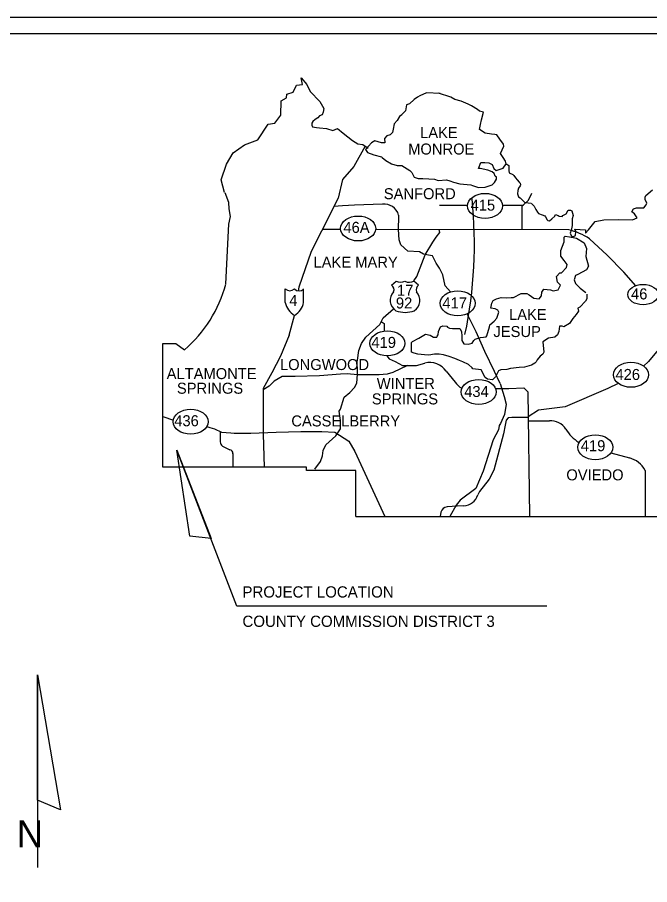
# Model space of a CAD drawing. Extents: x 2157516 to 2331756, y 2153820 to 2265756.
# Drawn here: x 2268726 to 2310288, y 2208739 to 2265756 of the extents above; entities that cross this region are included whole.
import ezdxf

# ---------------------------------------------------------------- set-up
doc = ezdxf.new("R2010")
doc.units = 0
for name, color, linetype in [('Default', 7, 'Continuous'), ('NorthArw_dp', 7, 'Continuous'), ('PlotBorder_dp', 7, 'Continuous'), ('SheetBorder_dp', 7, 'Continuous'), ('TextLabel', 7, 'Continuous')]:
    doc.layers.add(name, color=color, linetype=linetype)

msp = doc.modelspace()

# ---------------------------------------------------------------- linework, layer by layer
at = {"layer": 'Default'}
for p, q in [((2286861, 2260837), (2287074, 2261301)), ((2287074, 2261301), (2287461, 2261340)), ((2287461, 2261339), (2287384, 2261784)), ((2287384, 2261784), (2287751, 2261339)), ((2287751, 2261340), (2287984, 2260876)), ((2286436, 2260702), (2286861, 2260837)), ((2287984, 2260876), (2288603, 2260218)), ((2295622, 2260801), (2295179, 2260600)), ((2296508, 2260741), (2295622, 2260801)), ((2297212, 2260499), (2296407, 2260761)), ((2286049, 2259329), (2286068, 2260276)), ((2286068, 2260276), (2286417, 2260470)), ((2286417, 2260470), (2286436, 2260702)), ((2288603, 2260218), (2288873, 2259754)), ((2294817, 2260358), (2294494, 2260076)), ((2295038, 2260499), (2294817, 2260358)), ((2295179, 2260600), (2295038, 2260499)), ((2297474, 2260358), (2297212, 2260499)), ((2297897, 2260237), (2297474, 2260358)), ((2298360, 2260056), (2297897, 2260237)), ((2288873, 2259754), (2288835, 2259522)), ((2294233, 2259613), (2294031, 2259391)), ((2294313, 2259996), (2294233, 2259613)), ((2294494, 2260076), (2294313, 2259996)), ((2298581, 2259935), (2298360, 2260056)), ((2298964, 2259694), (2298581, 2259935)), ((2299105, 2259593), (2298964, 2259694)), ((2299366, 2259512), (2299105, 2259593)), ((2285643, 2258806), (2286049, 2259329)), ((2288293, 2259039), (2288138, 2258903)), ((2288486, 2259155), (2288293, 2259039)), ((2288583, 2259271), (2288486, 2259155)), ((2288757, 2259348), (2288583, 2259271)), ((2288835, 2259522), (2288757, 2259348)), ((2293850, 2259230), (2293689, 2258969)), ((2293991, 2259351), (2293850, 2259230)), ((2294031, 2259391), (2293991, 2259351)), ((2299165, 2258707), (2299225, 2259029)), ((2299225, 2259029), (2299366, 2259512)), ((2284539, 2257693), (2285216, 2258737)), ((2285216, 2258737), (2285643, 2258806)), ((2288138, 2258903), (2288080, 2258806)), ((2288080, 2258806), (2288080, 2258671)), ((2288080, 2258671), (2288119, 2258555)), ((2288119, 2258555), (2288390, 2258516)), ((2288390, 2258516), (2288583, 2258497)), ((2288583, 2258497), (2289048, 2258439)), ((2289048, 2258439), (2289454, 2258323)), ((2289454, 2258323), (2289763, 2258458)), ((2289763, 2258458), (2290150, 2258149)), ((2293488, 2258747), (2293427, 2258405)), ((2293689, 2258969), (2293488, 2258747)), ((2299105, 2258384), (2299165, 2258707)), ((2290150, 2258149), (2290750, 2257665)), ((2293005, 2257962), (2292864, 2257800)), ((2293226, 2258042), (2293005, 2257962)), ((2293387, 2258183), (2293226, 2258042)), ((2293427, 2258405), (2293387, 2258183)), ((2299487, 2258143), (2299105, 2258384)), ((2299890, 2258082), (2299487, 2258143)), ((2300111, 2258062), (2299890, 2258082)), ((2300252, 2258022), (2300111, 2258062)), ((2300433, 2257740), (2300252, 2258022)), ((2282914, 2256842), (2283649, 2257384)), ((2283649, 2257384), (2284539, 2257693)), ((2290750, 2257665), (2291098, 2257431)), ((2291098, 2257431), (2291426, 2257392)), ((2291426, 2257392), (2291794, 2257160)), ((2291998, 2257498), (2291616, 2257075)), ((2292220, 2257639), (2291998, 2257498)), ((2292662, 2257498), (2292220, 2257639)), ((2292884, 2257498), (2292662, 2257498)), ((2292864, 2257800), (2292884, 2257498)), ((2300675, 2257418), (2300433, 2257740)), ((2300695, 2257277), (2300675, 2257418)), ((2282469, 2256107), (2282914, 2256842)), ((2291587, 2257291), (2290854, 2255947)), ((2291616, 2257075), (2291736, 2256874)), ((2291736, 2256874), (2292159, 2256713)), ((2300494, 2256814), (2300695, 2257277)), ((2300655, 2256552), (2300494, 2256814)), ((2292159, 2256713), (2292662, 2256592)), ((2292662, 2256592), (2292703, 2256532)), ((2292703, 2256532), (2292944, 2256350)), ((2292944, 2256350), (2293327, 2256129)), ((2299044, 2255827), (2299185, 2256210)), ((2299185, 2256210), (2299447, 2256210)), ((2299447, 2256210), (2299708, 2256189)), ((2299708, 2256189), (2299930, 2256089)), ((2300816, 2256310), (2300655, 2256552)), ((2300856, 2256129), (2300816, 2256310)), ((2282121, 2255063), (2282469, 2256107)), ((2290854, 2255947), (2290107, 2255085)), ((2293327, 2256129), (2293689, 2256008)), ((2293689, 2256008), (2293951, 2256008)), ((2293951, 2256008), (2293991, 2256008)), ((2293991, 2256008), (2294172, 2255907)), ((2294172, 2255907), (2294515, 2255686)), ((2294515, 2255686), (2294655, 2255545)), ((2299145, 2255827), (2299044, 2255827)), ((2299648, 2255706), (2299145, 2255827)), ((2299930, 2255605), (2299648, 2255706)), ((2299930, 2256089), (2300051, 2255827)), ((2300071, 2255485), (2299930, 2255605)), ((2300051, 2255827), (2300192, 2255686)), ((2300192, 2255686), (2300655, 2255847)), ((2300655, 2255847), (2300856, 2256129)), ((2300856, 2256129), (2300897, 2256102)), ((2300897, 2256102), (2301032, 2256025)), ((2301032, 2256025), (2301032, 2255696)), ((2301032, 2255696), (2301052, 2255542)), ((2282353, 2254231), (2282121, 2255063)), ((2290107, 2255085), (2289820, 2253878)), ((2294655, 2255545), (2294817, 2255243)), ((2294817, 2255243), (2295078, 2255162)), ((2295078, 2255162), (2295380, 2255162)), ((2295380, 2255162), (2295783, 2255142)), ((2295783, 2255142), (2296145, 2255122)), ((2296145, 2255122), (2296387, 2255021)), ((2296387, 2255021), (2296930, 2255082)), ((2296930, 2255082), (2297152, 2255001)), ((2300131, 2255323), (2300071, 2255485)), ((2300091, 2254901), (2300212, 2255122)), ((2300212, 2255243), (2300131, 2255323)), ((2300212, 2255122), (2300212, 2255243)), ((2301052, 2255542), (2301303, 2255425)), ((2301303, 2255425), (2301361, 2255367)), ((2301361, 2255367), (2301477, 2255213)), ((2301477, 2255213), (2301574, 2255077)), ((2301574, 2255077), (2301709, 2254923)), ((2297152, 2255001), (2297393, 2254921)), ((2297393, 2254921), (2297816, 2254820)), ((2297816, 2254820), (2298541, 2254739)), ((2298541, 2254739), (2298642, 2254699)), ((2298642, 2254699), (2299044, 2254578)), ((2299044, 2254578), (2299487, 2254598)), ((2299487, 2254598), (2299930, 2254739)), ((2299930, 2254739), (2300091, 2254901)), ((2301671, 2254536), (2301613, 2254362)), ((2301787, 2254671), (2301671, 2254536)), ((2301709, 2254923), (2301787, 2254845)), ((2301787, 2254845), (2301806, 2254749)), ((2301806, 2254749), (2301787, 2254671)), ((2282624, 2253574), (2282391, 2254212)), ((2289820, 2253878), (2288728, 2251694)), ((2301613, 2254362), (2301593, 2254149)), ((2301593, 2254149), (2301613, 2254091)), ((2301613, 2254091), (2301671, 2253956)), ((2301671, 2253956), (2301768, 2253898)), ((2301768, 2253898), (2301864, 2253801)), ((2302328, 2253731), (2302536, 2254206)), ((2309996, 2253944), (2310030, 2254044)), ((2309996, 2253776), (2309996, 2253944)), ((2310030, 2254044), (2310465, 2254412)), ((2282643, 2253168), (2282624, 2253574)), ((2290107, 2253374), (2289534, 2253330)), ((2290879, 2253418), (2290107, 2253374)), ((2292732, 2253485), (2290879, 2253418)), ((2296479, 2253412), (2298323, 2253412)), ((2300622, 2253412), (2301994, 2253412)), ((2301864, 2253801), (2302058, 2253608)), ((2301913, 2253346), (2302328, 2253731)), ((2301913, 2251804), (2301913, 2253346)), ((2302058, 2253608), (2302309, 2253569)), ((2302309, 2253569), (2302503, 2253530)), ((2302522, 2253511), (2302691, 2253338)), ((2302691, 2253338), (2302807, 2253125)), ((2309896, 2253241), (2310063, 2253441)), ((2310097, 2253542), (2309996, 2253776)), ((2310063, 2253441), (2310097, 2253542)), ((2282740, 2252665), (2282643, 2253168)), ((2293784, 2251729), (2293791, 2252757)), ((2302807, 2253125), (2302923, 2252951)), ((2302923, 2252951), (2302981, 2252854)), ((2302981, 2252854), (2303213, 2252777)), ((2303213, 2252777), (2303406, 2252699)), ((2304064, 2252680), (2304103, 2252796)), ((2304103, 2252796), (2304277, 2252738)), ((2304277, 2252738), (2304335, 2252680)), ((2304586, 2252719), (2304799, 2252835)), ((2304799, 2252835), (2304935, 2253086)), ((2304935, 2253086), (2305089, 2253086)), ((2305089, 2253086), (2305167, 2253028)), ((2305167, 2253028), (2305264, 2252738)), ((2305264, 2252738), (2305206, 2252506)), ((2309126, 2252973), (2309226, 2253174)), ((2309293, 2252839), (2309126, 2252973)), ((2309226, 2253174), (2309427, 2253241)), ((2309461, 2252571), (2309293, 2252839)), ((2309427, 2253241), (2309661, 2253241)), ((2309661, 2253241), (2309896, 2253241)), ((2282421, 2248226), (2282628, 2252165)), ((2282628, 2252165), (2282740, 2252665)), ((2303406, 2252699), (2303445, 2252641)), ((2303445, 2252641), (2303542, 2252448)), ((2303542, 2252448), (2303600, 2252390)), ((2303600, 2252390), (2303716, 2252371)), ((2303716, 2252371), (2303851, 2252506)), ((2303851, 2252506), (2304064, 2252680)), ((2304335, 2252680), (2304528, 2252661)), ((2304528, 2252661), (2304586, 2252719)), ((2305206, 2252506), (2305186, 2252216)), ((2305186, 2252216), (2305206, 2252081)), ((2306270, 2251790), (2306716, 2252337)), ((2306716, 2252337), (2307285, 2252437)), ((2307285, 2252437), (2308222, 2252471)), ((2308222, 2252471), (2309159, 2252437)), ((2309159, 2252437), (2309461, 2252571)), ((2288728, 2251694), (2288039, 2250372)), ((2289980, 2251802), (2288782, 2251802)), ((2304966, 2251796), (2292275, 2251801)), ((2293823, 2251130), (2293779, 2251800)), ((2296263, 2251300), (2296492, 2251622)), ((2296492, 2251622), (2296446, 2251805)), ((2305128, 2251752), (2305070, 2251558)), ((2305206, 2252081), (2305128, 2251752)), ((2305438, 2251674), (2305360, 2251829)), ((2305360, 2251829), (2306076, 2251790)), ((2305418, 2251423), (2305438, 2251674)), ((2306076, 2251790), (2306076, 2251578)), ((2306076, 2251578), (2306270, 2251790)), ((2293935, 2250794), (2293823, 2251130)), ((2296033, 2250979), (2296263, 2251300)), ((2304671, 2251305), (2304733, 2251368)), ((2304671, 2250994), (2304671, 2251305)), ((2304733, 2251368), (2305013, 2251336)), ((2305013, 2251336), (2305480, 2251243)), ((2305070, 2251558), (2305128, 2251404)), ((2305128, 2251404), (2305244, 2251326)), ((2305244, 2251326), (2305418, 2251423)), ((2305480, 2251243), (2305979, 2250932)), ((2307505, 2250127), (2306339, 2251204)), ((2294383, 2250384), (2293935, 2250794)), ((2295530, 2250144), (2296033, 2250979)), ((2304453, 2250433), (2304671, 2250994)), ((2305979, 2250932), (2306134, 2250558)), ((2306134, 2250558), (2306103, 2250028)), ((2288039, 2250372), (2287234, 2248016)), ((2295166, 2250347), (2294383, 2250384)), ((2294979, 2248721), (2295530, 2250144)), ((2295426, 2250198), (2295166, 2250347)), ((2295762, 2250123), (2295426, 2250198)), ((2296023, 2250086), (2295762, 2250123)), ((2296247, 2249601), (2296023, 2250086)), ((2304453, 2250059), (2304453, 2250433)), ((2304671, 2249779), (2304453, 2250059)), ((2306103, 2250028), (2306259, 2249405)), ((2308582, 2249005), (2307505, 2250127)), ((2296470, 2249265), (2296247, 2249601)), ((2304858, 2249498), (2304671, 2249779)), ((2304827, 2249312), (2304858, 2249498)), ((2306259, 2249405), (2306134, 2249156)), ((2296694, 2248818), (2296470, 2249265)), ((2296843, 2248109), (2296694, 2248818)), ((2304173, 2248720), (2304391, 2248969)), ((2304391, 2248969), (2304484, 2248969)), ((2304484, 2248969), (2304827, 2249312)), ((2305418, 2248782), (2305325, 2248502)), ((2305574, 2248844), (2305418, 2248782)), ((2306134, 2249156), (2305574, 2248844)), ((2309370, 2248116), (2308582, 2249005)), ((2293323, 2248147), (2293628, 2248417)), ((2294784, 2248427), (2294979, 2248721)), ((2295101, 2248147), (2294796, 2248417)), ((2304235, 2248346), (2304173, 2248720)), ((2304422, 2248159), (2304235, 2248346)), ((2305325, 2248502), (2305418, 2248252)), ((2305418, 2248252), (2305730, 2247941)), ((2286337, 2247013), (2286337, 2247912)), ((2287234, 2248016), (2287187, 2247780)), ((2287543, 2247013), (2287543, 2247912)), ((2297199, 2247705), (2296843, 2248109)), ((2303176, 2247442), (2303207, 2247692)), ((2303207, 2247692), (2303332, 2247878)), ((2303332, 2247878), (2303768, 2247847)), ((2303768, 2247847), (2303955, 2247785)), ((2303955, 2247785), (2304266, 2247847)), ((2304266, 2247847), (2304422, 2248159)), ((2305730, 2247941), (2306103, 2247660)), ((2299907, 2246975), (2300000, 2247131)), ((2300000, 2247131), (2300218, 2247255)), ((2300218, 2247255), (2300530, 2247349)), ((2300530, 2247349), (2300903, 2247318)), ((2300903, 2247318), (2301183, 2247349)), ((2301183, 2247349), (2301339, 2247349)), ((2301339, 2247349), (2301837, 2247598)), ((2301837, 2247598), (2302211, 2247598)), ((2302211, 2247598), (2302367, 2247505)), ((2302367, 2247505), (2302678, 2247287)), ((2302678, 2247287), (2303021, 2247255)), ((2303021, 2247255), (2303176, 2247442)), ((2306072, 2247100), (2305698, 2246695)), ((2306166, 2247255), (2306072, 2247100)), ((2306166, 2247567), (2306166, 2247255)), ((2292776, 2246012), (2293453, 2246599)), ((2299844, 2246632), (2299907, 2246975)), ((2300125, 2246601), (2299844, 2246632)), ((2300312, 2246508), (2300125, 2246601)), ((2300374, 2246383), (2300312, 2246508)), ((2305698, 2246695), (2305574, 2246632)), ((2305574, 2246632), (2305605, 2246445)), ((2286602, 2244855), (2286940, 2246160)), ((2292547, 2245553), (2292776, 2246012)), ((2298894, 2245088), (2298288, 2246263)), ((2300062, 2245791), (2300249, 2245978)), ((2300249, 2245978), (2300374, 2246383)), ((2305231, 2245947), (2305013, 2245635)), ((2305449, 2246227), (2305231, 2245947)), ((2305605, 2246445), (2305449, 2246227)), ((2291629, 2244726), (2292547, 2245553)), ((2292647, 2245754), (2292846, 2245635)), ((2292846, 2245635), (2292846, 2245134)), ((2296419, 2245106), (2296544, 2245417)), ((2296544, 2245417), (2296700, 2245480)), ((2296700, 2245480), (2296949, 2245448)), ((2296949, 2245448), (2297011, 2245386)), ((2297011, 2245386), (2297135, 2245324)), ((2297135, 2245324), (2297322, 2245293)), ((2299595, 2244825), (2299751, 2245417)), ((2299751, 2245417), (2299782, 2245542)), ((2299782, 2245542), (2300062, 2245791)), ((2304360, 2245448), (2304328, 2245106)), ((2304546, 2245448), (2304360, 2245448)), ((2304640, 2245417), (2304546, 2245448)), ((2305013, 2245635), (2304640, 2245417)), ((2286602, 2244855), (2286028, 2243476)), ((2295124, 2244659), (2295558, 2244930)), ((2295558, 2244930), (2295859, 2244857)), ((2295859, 2244857), (2296077, 2244732)), ((2296295, 2244732), (2296326, 2244794)), ((2296326, 2244794), (2296388, 2244888)), ((2296388, 2244888), (2296419, 2245106)), ((2297322, 2245293), (2297571, 2245293)), ((2297571, 2245293), (2297821, 2245293)), ((2297821, 2245293), (2297914, 2245106)), ((2297914, 2245106), (2297945, 2244794)), ((2297945, 2244794), (2297945, 2244670)), ((2299453, 2243783), (2298894, 2245088)), ((2299377, 2244732), (2299533, 2244763)), ((2299533, 2244763), (2299595, 2244825)), ((2304235, 2244888), (2304048, 2244732)), ((2304328, 2245106), (2304235, 2244888)), ((2278294, 2236185), (2278294, 2244325)), ((2278294, 2244325), (2279159, 2244325)), ((2278294, 2244325), (2279140, 2244325)), ((2279140, 2244325), (2279703, 2243894)), ((2291170, 2243854), (2291353, 2244313)), ((2291353, 2244313), (2291629, 2244726)), ((2294636, 2244387), (2294690, 2244441)), ((2294636, 2244224), (2294636, 2244387)), ((2294636, 2244007), (2294636, 2244224)), ((2294690, 2244441), (2295124, 2244659)), ((2296077, 2244732), (2296170, 2244732)), ((2296170, 2244732), (2296295, 2244732)), ((2297945, 2244670), (2297945, 2244514)), ((2297945, 2244514), (2298070, 2244296)), ((2298070, 2244296), (2298350, 2244265)), ((2298350, 2244265), (2298630, 2244327)), ((2298630, 2244327), (2298724, 2244514)), ((2298724, 2244514), (2298817, 2244607)), ((2298817, 2244607), (2299159, 2244701)), ((2299159, 2244701), (2299377, 2244732)), ((2303643, 2244670), (2303270, 2244420)), ((2303270, 2244420), (2303332, 2243735)), ((2304048, 2244732), (2303643, 2244670)), ((2291078, 2243211), (2291170, 2243854)), ((2294644, 2243735), (2294644, 2244078)), ((2294800, 2243673), (2294644, 2243735)), ((2295049, 2243610), (2294800, 2243673)), ((2300086, 2242478), (2299453, 2243783)), ((2303332, 2243735), (2303270, 2243610)), ((2310855, 2243899), (2310204, 2243139)), ((2286028, 2243476), (2285453, 2242384)), ((2291032, 2243028), (2291078, 2243211)), ((2293009, 2243504), (2293171, 2243302)), ((2293171, 2243302), (2293551, 2243139)), ((2293551, 2243139), (2294039, 2242867)), ((2295485, 2243579), (2295049, 2243610)), ((2295765, 2243548), (2295485, 2243579)), ((2296139, 2243610), (2295765, 2243548)), ((2296450, 2243610), (2296139, 2243610)), ((2296731, 2243579), (2296450, 2243610)), ((2297104, 2243455), (2296731, 2243579)), ((2297478, 2243330), (2297104, 2243455)), ((2297789, 2243205), (2297478, 2243330)), ((2298007, 2243112), (2297789, 2243205)), ((2298381, 2242925), (2298007, 2243112)), ((2302834, 2243112), (2302740, 2243019)), ((2302896, 2243237), (2302834, 2243112)), ((2303083, 2243486), (2302896, 2243237)), ((2303270, 2243610), (2303083, 2243486)), ((2310204, 2243139), (2309880, 2242833)), ((2291078, 2242706), (2291032, 2243028)), ((2291078, 2242293), (2291078, 2242706)), ((2294375, 2242867), (2293398, 2242402)), ((2294039, 2242867), (2294419, 2242867)), ((2294419, 2242867), (2294961, 2242867)), ((2294961, 2242867), (2295504, 2243030)), ((2296914, 2242488), (2297511, 2241782)), ((2298630, 2242707), (2298381, 2242925)), ((2298661, 2242645), (2298630, 2242707)), ((2299222, 2242582), (2298661, 2242645)), ((2299471, 2242084), (2299222, 2242582)), ((2300459, 2241694), (2300086, 2242478)), ((2300343, 2242520), (2300156, 2242115)), ((2300498, 2242582), (2300343, 2242520)), ((2300903, 2242614), (2300498, 2242582)), ((2301152, 2242676), (2300903, 2242614)), ((2301713, 2242738), (2301152, 2242676)), ((2302055, 2242769), (2301713, 2242738)), ((2302211, 2242800), (2302055, 2242769)), ((2302522, 2242894), (2302211, 2242800)), ((2302740, 2243019), (2302522, 2242894)), ((2285453, 2242384), (2284883, 2241351)), ((2286128, 2242141), (2285606, 2241843)), ((2286986, 2242141), (2286128, 2242141)), ((2288589, 2242178), (2286986, 2242141)), ((2289968, 2242290), (2288589, 2242178)), ((2290416, 2242328), (2289968, 2242290)), ((2291087, 2242253), (2290416, 2242328)), ((2291032, 2241696), (2291078, 2242293)), ((2291832, 2242253), (2291087, 2242253)), ((2292503, 2242253), (2291832, 2242253)), ((2293025, 2242290), (2292503, 2242253)), ((2293398, 2242402), (2293025, 2242290)), ((2299627, 2241959), (2299471, 2242084)), ((2299969, 2241928), (2299627, 2241959)), ((2300156, 2242115), (2299969, 2241928)), ((2285271, 2241507), (2284883, 2241268)), ((2284883, 2241351), (2284883, 2238362)), ((2285606, 2241843), (2285271, 2241507)), ((2290573, 2241099), (2290894, 2241421)), ((2290894, 2241421), (2291032, 2241696)), ((2300161, 2241348), (2301037, 2241348)), ((2300459, 2241694), (2300718, 2240841)), ((2301037, 2241348), (2302013, 2241402)), ((2302013, 2241402), (2302284, 2241131)), ((2307546, 2241348), (2304726, 2240154)), ((2308219, 2241695), (2307546, 2241348)), ((2289977, 2239997), (2290206, 2240778)), ((2290206, 2240778), (2290573, 2241099)), ((2300718, 2240841), (2300867, 2240318)), ((2302284, 2241131), (2302391, 2232944)), ((2300867, 2240318), (2300755, 2239647)), ((2289885, 2239860), (2289977, 2239997)), ((2289977, 2239263), (2289885, 2239860)), ((2300755, 2239647), (2300481, 2239046)), ((2302990, 2239937), (2302306, 2239494)), ((2304726, 2240154), (2302990, 2239937)), ((2278294, 2239522), (2278980, 2239282)), ((2289977, 2238712), (2289977, 2239263)), ((2300867, 2239274), (2300792, 2238939)), ((2300979, 2239423), (2300867, 2239274)), ((2301227, 2239456), (2300979, 2239423)), ((2302271, 2239456), (2301227, 2239456)), ((2302309, 2239231), (2303695, 2239231)), ((2281185, 2238857), (2281369, 2238791)), ((2281369, 2238791), (2281675, 2238706)), ((2281675, 2238706), (2282150, 2238486)), ((2282060, 2238527), (2282060, 2237840)), ((2282150, 2238486), (2282750, 2238448)), ((2285745, 2238477), (2287353, 2238535)), ((2287353, 2238535), (2288732, 2238535)), ((2288732, 2238535), (2289594, 2238477)), ((2289655, 2238253), (2289977, 2238712)), ((2300357, 2238634), (2300006, 2237983)), ((2300407, 2238934), (2300357, 2238634)), ((2300481, 2239046), (2300407, 2238934)), ((2300792, 2238939), (2300680, 2238379)), ((2282750, 2238448), (2282987, 2238420)), ((2282987, 2238420), (2284078, 2238420)), ((2284078, 2238420), (2285745, 2238477)), ((2284883, 2238362), (2284940, 2236178)), ((2289013, 2237656), (2289655, 2238253)), ((2289594, 2238477), (2290513, 2237903)), ((2300006, 2237983), (2299355, 2235920)), ((2300680, 2238379), (2300047, 2235992)), ((2282204, 2237573), (2282474, 2237423)), ((2282474, 2237423), (2282684, 2237333)), ((2288829, 2237289), (2289013, 2237656)), ((2290513, 2237903), (2290916, 2237213)), ((2283159, 2227056), (2279217, 2237311)), ((2282900, 2237072), (2282900, 2236196)), ((2288646, 2236554), (2288783, 2236921)), ((2288783, 2236921), (2288829, 2237289)), ((2290916, 2237213), (2292881, 2232944)), ((2307743, 2237126), (2308957, 2236789)), ((2288278, 2236049), (2288646, 2236554)), ((2287727, 2236185), (2278294, 2236185)), ((2287727, 2235969), (2287727, 2236185)), ((2290968, 2235969), (2287727, 2235969)), ((2290968, 2232944), (2290968, 2235969)), ((2299355, 2235920), (2298867, 2234781)), ((2300047, 2235992), (2299748, 2235396)), ((2309988, 2235975), (2309988, 2232935)), ((2299748, 2235396), (2299095, 2234584)), ((2298867, 2234781), (2297836, 2234021)), ((2299095, 2234584), (2298987, 2234368)), ((2297836, 2234021), (2297565, 2233695)), ((2297631, 2233627), (2296971, 2233578)), ((2297565, 2233695), (2297165, 2232944)), ((2298063, 2233643), (2297631, 2233627)), ((2290968, 2232944), (2323515, 2232944)), ((2296568, 2233226), (2296515, 2232944)), ((2303540, 2227056), (2283159, 2227056))]:
    msp.add_line(p, q, dxfattribs=at)
msp.add_lwpolyline([(2279217, 2237311), (2281456, 2231487), (2280073, 2231648)], close=True, dxfattribs=at)
for centre, radius, start, end in [((2292818, 2252476), 1012, 16.0958, 94.902), ((2269936, 2250856), 28834, 348.105, 5.8904), ((2303688, 2246949), 5013, 58.0781, 75.228), ((2274239, 2250342), 8452, 310.2757, 345.4975), ((2293922, 2249045), 694, 244.9344, 293.0494), ((2294484, 2249030), 688, 244.9903, 296.9038), ((2286645, 2248227), 440, 225.6466, 312.1907), ((2287248, 2248216), 440, 225.6466, 312.1907), ((2294053, 2247152), 816, 136.8231, 236.7608), ((2293122, 2247846), 363, 338.0393, 56.3707), ((2294370, 2247152), 816, 303.2392, 43.1769), ((2295301, 2247846), 363, 123.6293, 201.9607), ((2287615, 2247278), 1306, 191.7069, 238.8545), ((2286265, 2247278), 1306, 301.1455, 348.2931), ((2294212, 2248095), 1734, 249.5588, 290.4412), ((2295829, 2241772), 1300, 33.4009, 104.5043), ((2298406, 2242297), 1033, 209.9127, 243.9307), ((2303786, 2238058), 1176, 32.3827, 94.4635), ((2307076, 2240068), 2679, 210.9998, 237.3688), ((2282543, 2237928), 491, 190.3035, 226.3714), ((2282640, 2237076), 261, 358.9491, 80.1831), ((2308621, 2235304), 1522, 26.133, 77.2579), ((2298041, 2234622), 980, 271.2633, 344.9649), ((2297025, 2233109), 472, 96.5984, 165.6975)]:
    msp.add_arc(centre, radius, start, end, dxfattribs=at)
for centre, major_axis, ratio in [((2299473, 2253362), (1152, 0), 0.712693), ((2291128, 2251875), (1152, 0), 0.712693), ((2309856, 2247530), (1004, 0), 0.66697), ((2297669, 2246955), (1152, 0), 0.712693), ((2293053, 2244324), (1152, 0), 0.712693), ((2309061, 2242256), (1152, 0), 0.712693), ((2299050, 2241131), (1152, 0), 0.712693), ((2280121, 2239172), (1152, 0), 0.712693), ((2306712, 2237492), (1152, 0), 0.712693)]:
    msp.add_ellipse(centre, major_axis=major_axis, ratio=ratio, dxfattribs=at)
at = {"layer": 'NorthArw_dp'}
msp.add_line((2270050, 2222530), (2270050, 2209858), dxfattribs=at)
msp.add_lwpolyline([(2270050, 2214293), (2270050, 2222530), (2271571, 2213660)], close=True, dxfattribs=at)
at = {"layer": 'PlotBorder_dp'}
msp.add_lwpolyline([(2157516, 2153820), (2331756, 2153820), (2331756, 2265756), (2157516, 2265756)], close=True, dxfattribs=at)
at = {"layer": 'SheetBorder_dp'}
msp.add_line((2163324, 2264700), (2325948, 2264700), dxfattribs=at)

# ---------------------------------------------------------------- texts
at = {"layer": 'Default'}
for s, height, p in [('LAKE', 723.6, (2295198, 2257819)), ('MONROE', 723.6, (2294414, 2256738)), ('SANFORD', 723.6, (2292812, 2253801)), ('415', 723.6, (2298518, 2253050)), ('46A', 723.6, (2290159, 2251587)), ('LAKE MARY', 723.6, (2288193, 2249297)), ('17', 723.6, (2293683, 2247450)), ('46', 723.6, (2309066, 2247213)), ('4', 724, (2286595, 2246781)), ('92', 723.6, (2293609, 2246618)), ('417', 723.6, (2296666, 2246618)), ('LAKE ', 723.6, (2301046, 2245862)), ('JESUP', 723.6, (2300020, 2244739)), ('419', 723.6, (2292000, 2244026)), ('LONGWOOD', 723.6, (2285990, 2242568)), ('ALTAMONTE', 723.6, (2278541, 2241974)), ('426', 723.6, (2308040, 2241917)), ('WINTER ', 723.6, (2292351, 2241326)), ('SPRINGS', 723.6, (2279214, 2241013)), ('434', 723.6, (2298097, 2240797)), ('SPRINGS', 723.6, (2292027, 2240311)), ('436', 723.6, (2279040, 2238875)), ('CASSELBERRY', 723.65, (2286735, 2238864)), ('419', 723.6, (2305761, 2237233)), ('OVIEDO', 723.6, (2304812, 2235317))]:
    msp.add_text(s, height=height, rotation=0, dxfattribs=at).set_placement(p)
at = {"layer": 'NorthArw_dp'}
msp.add_text('N', height=1773, dxfattribs=at).set_placement((2268693, 2211189))
at = {"layer": 'TextLabel'}
for s, p in [('PROJECT LOCATION', (2283522, 2227613)), ('COUNTY COMMISSION DISTRICT 3', (2283522, 2225683))]:
    msp.add_text(s, height=739.2, dxfattribs=at).set_placement(p)

doc.saveas('drawing.dxf')
